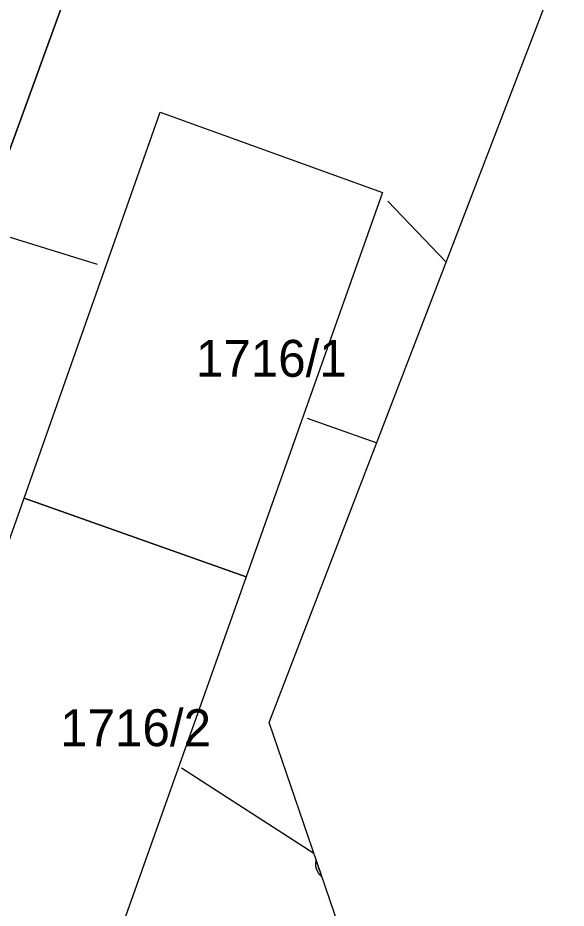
# Model space of a CAD drawing. Extents: x -562248 to -562040, y -1079385 to -1079027.
# Drawn here: x -562111.72 to -562089.43, y -1079101.77 to -1079065.59 of the extents above; entities that cross this region are included whole.
import ezdxf

# ---------------------------------------------------------------- set-up
doc = ezdxf.new("R2010")
doc.units = 0
for name, color, linetype in [('Kanalizační přípojka', 7, 'Continuous'), ('Kanalizační šachta', 7, 'Continuous'), ('Parcela-polygon', 7, 'Continuous'), ('Parcela-text', 7, 'Continuous'), ('Vodovodní přípojka', 7, 'Continuous')]:
    doc.layers.add(name, color=color, linetype=linetype)

msp = doc.modelspace()

# ---------------------------------------------------------------- linework, layer by layer
at = {"layer": 'Kanalizační přípojka'}
for points in [[(-562096.68, -1079073.04), (-562094.307, -1079075.526)], [(-562099.96, -1079081.86), (-562097.129, -1079082.863)], [(-562105.06, -1079096.07), (-562099.685, -1079099.532)]]:
    msp.add_lwpolyline(points, dxfattribs=at)
at = {"layer": 'Kanalizační šachta'}
for p, q in [((-562099.503, -1079100.065), (-562099.591, -1079099.808)), ((-562099.36, -1079100.484), (-562099.448, -1079100.226))]:
    msp.add_line(p, q, dxfattribs=at)
for points in [[(-562099.591, -1079099.808), (-562099.607, -1079099.864), (-562099.615, -1079099.921), (-562099.615, -1079099.98)], [(-562099.615, -1079099.98), (-562099.615, -1079100.087), (-562099.587, -1079100.191), (-562099.532, -1079100.29)], [(-562099.448, -1079100.226), (-562099.475, -1079100.174), (-562099.494, -1079100.12), (-562099.503, -1079100.065)], [(-562099.532, -1079100.29), (-562099.488, -1079100.368), (-562099.431, -1079100.433), (-562099.36, -1079100.484)]]:
    msp.add_open_spline(points, degree=2, dxfattribs=at)
at = {"layer": 'Parcela-polygon'}
for points in [[(-562122.69, -1079105.05), (-562122.05, -1079101.16), (-562121.03, -1079096.76), (-562119.65, -1079091.82), (-562106.84, -1079056.62), (-562116.62, -1079052.94), (-562116.47, -1079053.33), (-562127.9, -1079084.66), (-562129.6, -1079089.95), (-562131.3, -1079096.35), (-562132.29, -1079100.17), (-562132.68, -1079103.22)], [(-562089.427, -1079062.836), (-562106.84, -1079056.62), (-562119.65, -1079091.82), (-562121.03, -1079096.76), (-562122.05, -1079101.16), (-562122.69, -1079105.05), (-562122.92, -1079108.96), (-562097.98, -1079104.526)], [(-562097.98, -1079104.526), (-562101.498, -1079094.222), (-562089.427, -1079062.836)], [(-562117.01, -1079100.74), (-562111.46, -1079085.11), (-562105.93, -1079069.43), (-562096.89, -1079072.69), (-562102.44, -1079088.31), (-562107.99, -1079103.94), (-562117.01, -1079100.74)]]:
    msp.add_lwpolyline(points, dxfattribs=at)
for points in [[(-562111.46, -1079085.11), (-562105.93, -1079069.43), (-562096.89, -1079072.69), (-562102.44, -1079088.31)], [(-562111.46, -1079085.11), (-562102.44, -1079088.31), (-562107.99, -1079103.94), (-562117.01, -1079100.74)]]:
    msp.add_lwpolyline(points, close=True, dxfattribs=at)
at = {"layer": 'Vodovodní přípojka'}
msp.add_lwpolyline([(-562119.925, -1079072.045), (-562119.759, -1079072.126), (-562108.493, -1079075.605)], dxfattribs=at)

# ---------------------------------------------------------------- texts
at = {"layer": 'Parcela-text'}
for s, p in [('1716/1', (-562104.48, -1079080.18)), ('1716/2', (-562110, -1079095.19))]:
    msp.add_text(s, height=1.5, dxfattribs=at).set_placement(p)

doc.saveas('drawing.dxf')
